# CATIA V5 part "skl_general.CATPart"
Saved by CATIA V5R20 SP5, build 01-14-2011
Part number: skl_general
Publications: "Plan_ref", "Point.1", "Point.2", "Point.3", "Point.4", "Point.5", "L_bielles", "R_exentrique"
Bounding box of the stored display mesh (mm): x 0 to 0, y -90 to 90, z 0 to 100
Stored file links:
  U:\2A\IAO\ThinkMotion\skl_general.CATPart
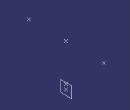
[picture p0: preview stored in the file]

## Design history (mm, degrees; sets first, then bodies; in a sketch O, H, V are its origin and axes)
Parameters
  L_bielles = 90 mm {= 9*R_exentrique}
  R_exentrique = 10 mm
Set1
  Plane1 "Plan_ref": type Offset, RefPlane yz-plane, Offset 0
  Point1: (0, 0, 10 {= R_exentrique})
  Point2: (0, 0, 0)
  Point3: (0, 0, 100 {= R_exentrique +L_bielles})
  Point4: (0, -90 {= -L_bielles}, 100 {= R_exentrique +L_bielles})
  Point5: (0, 90 {= L_bielles}, 100 {= R_exentrique + L_bielles})
Body1 (main body)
